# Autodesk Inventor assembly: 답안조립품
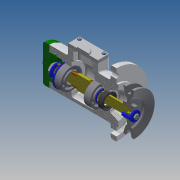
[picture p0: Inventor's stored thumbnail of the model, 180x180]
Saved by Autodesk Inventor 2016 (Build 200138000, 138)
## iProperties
Created: 2017-05
Part Number: 답안조립품
Document SubType Name: Assembly
Designer: Administrator
Author: Administrator
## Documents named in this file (20)
- D:\470507V1002\답안조립품.iam
- D:\470507V1002\본체.ipt
- D:\470507V1002\축.ipt
- D:\470507V1002\베어링 15 x 35 x 11.ipt
- D:\470507V1002\부시1.ipt
- D:\470507V1002\멈춤링 15 x 1.ipt
- D:\470507V1002\멈춤링 35x1.6.ipt
- D:\470507V1002\부시2.ipt
- D:\470507V1002\와셔 10x21.ipt
- D:\470507V1002\너트 M10.ipt
- D:\470507V1002\사이드 커버.ipt
- 사이드 커버.ipt
- D:\470507V1002\키 4 x 4 x 18.ipt
- D:\470507V1002\V-벨트풀리.ipt
- D:\470507V1002\볼트 M4 x 10.ipt
- D:\470507V1002\와셔 4x16.ipt
- D:\470507V1002\탑 커버.ipt
- D:\470507V1002\오일 실 15 25 7.ipt
- D:\470507V1002\십자볼트 M3 x 10.ipt
- D:\470507V1002\와셔 3x6.ipt
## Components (2 placed, 2 different names)
1. V-벨트풀리:1
2. ISO 4017 M4 x 10:1
